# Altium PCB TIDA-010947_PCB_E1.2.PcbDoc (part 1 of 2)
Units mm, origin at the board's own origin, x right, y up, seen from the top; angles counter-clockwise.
Board outline 34 x 34 mm, 4 copper layers (Top Layer, GND, PWR, Bottom Layer), stack 1.787 mm thick; 64 components, 51 nets, 201 pads, 60 vias.
Unrouted connection lines stored in the file: 1.
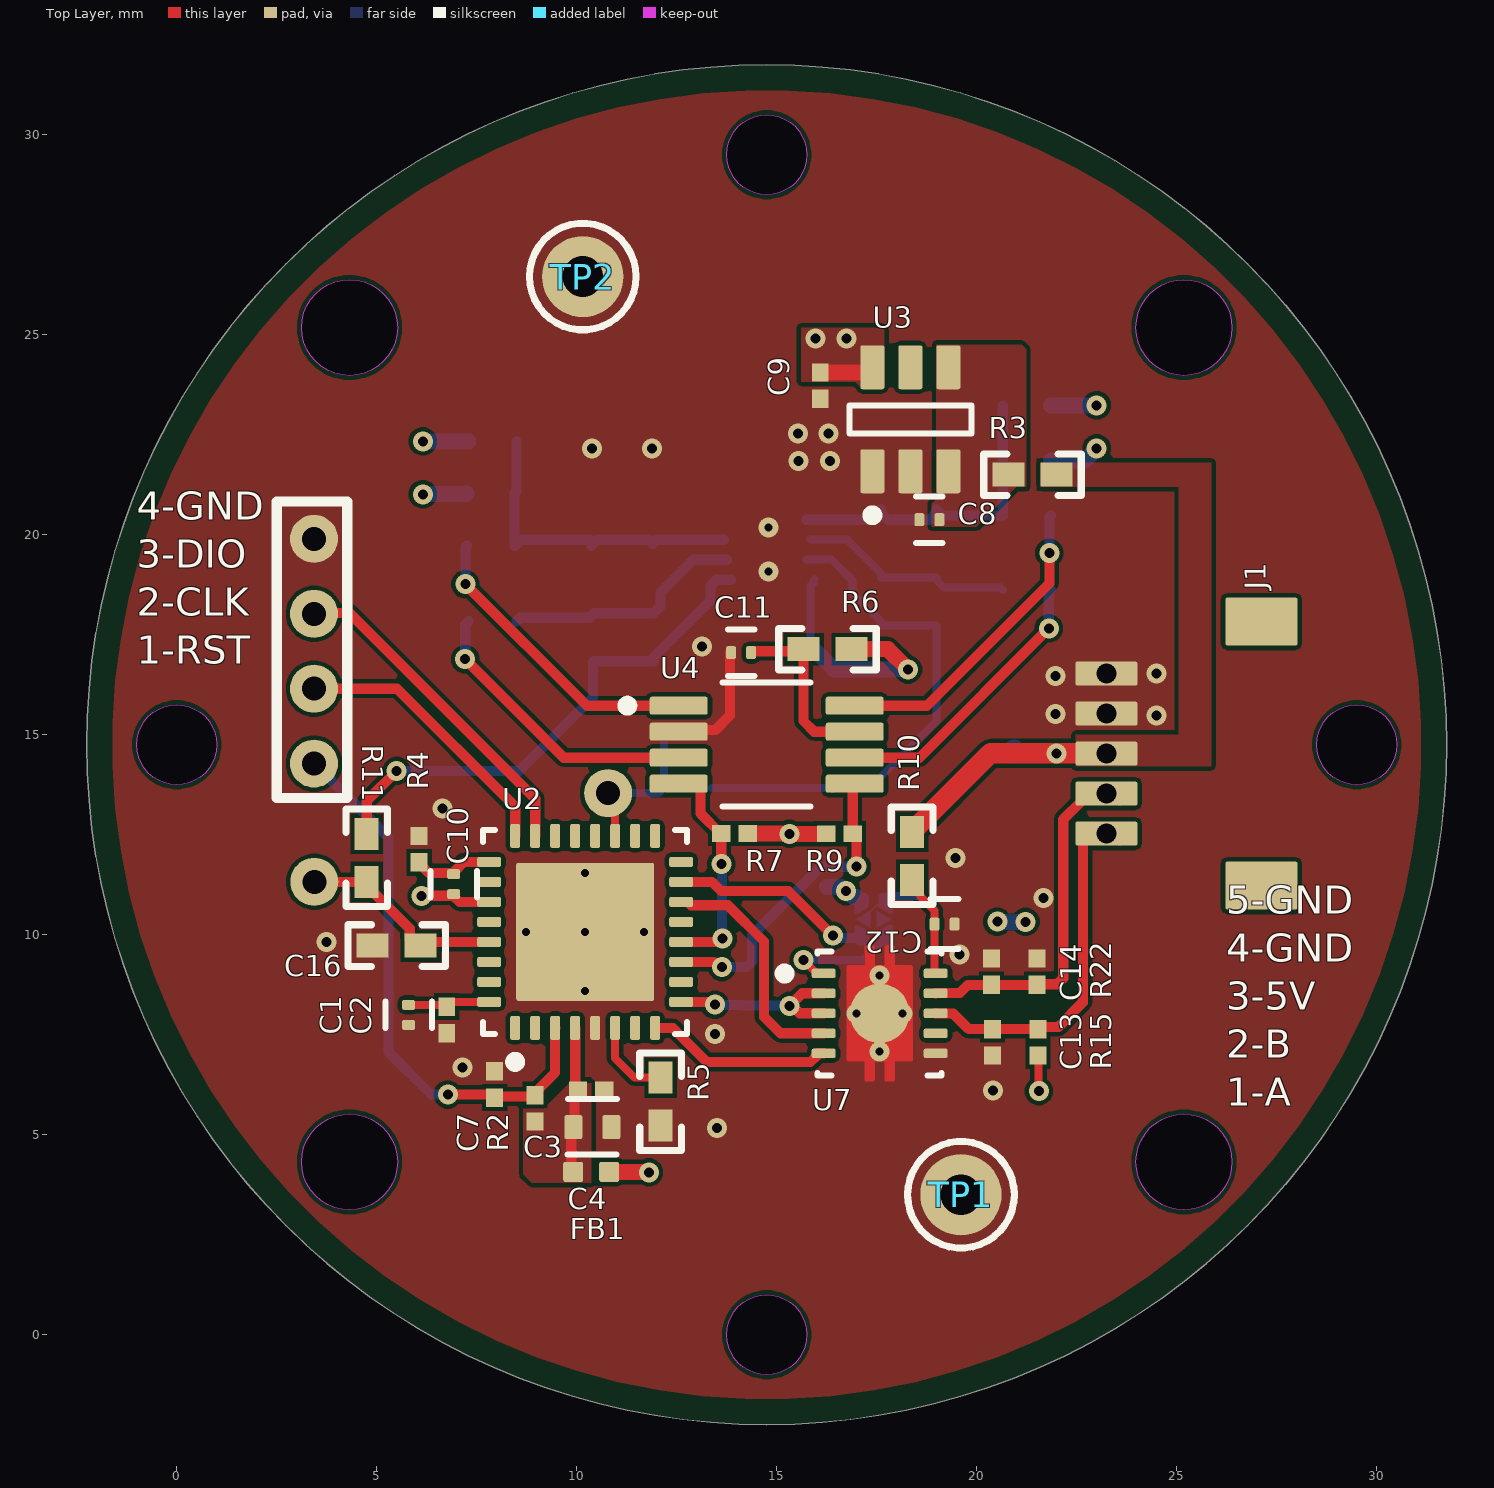
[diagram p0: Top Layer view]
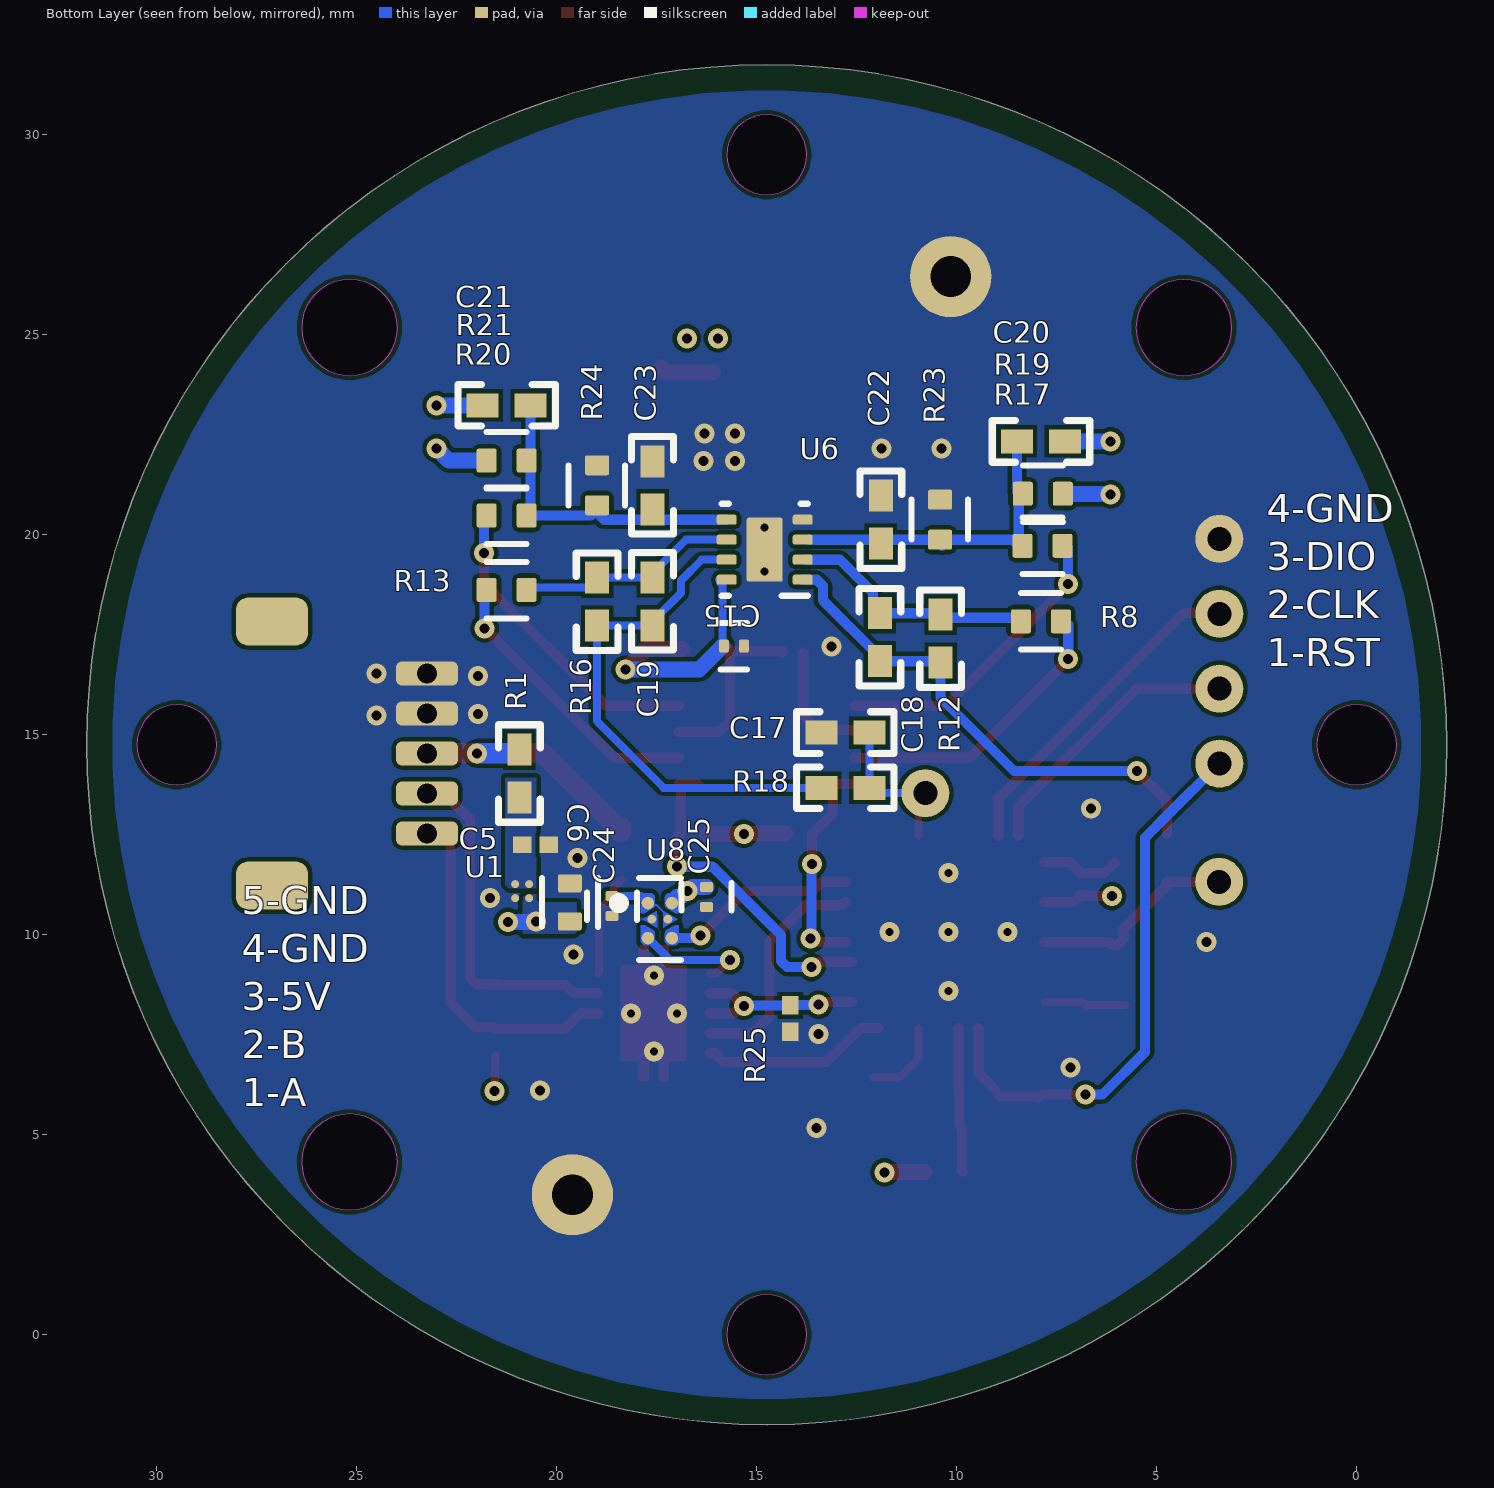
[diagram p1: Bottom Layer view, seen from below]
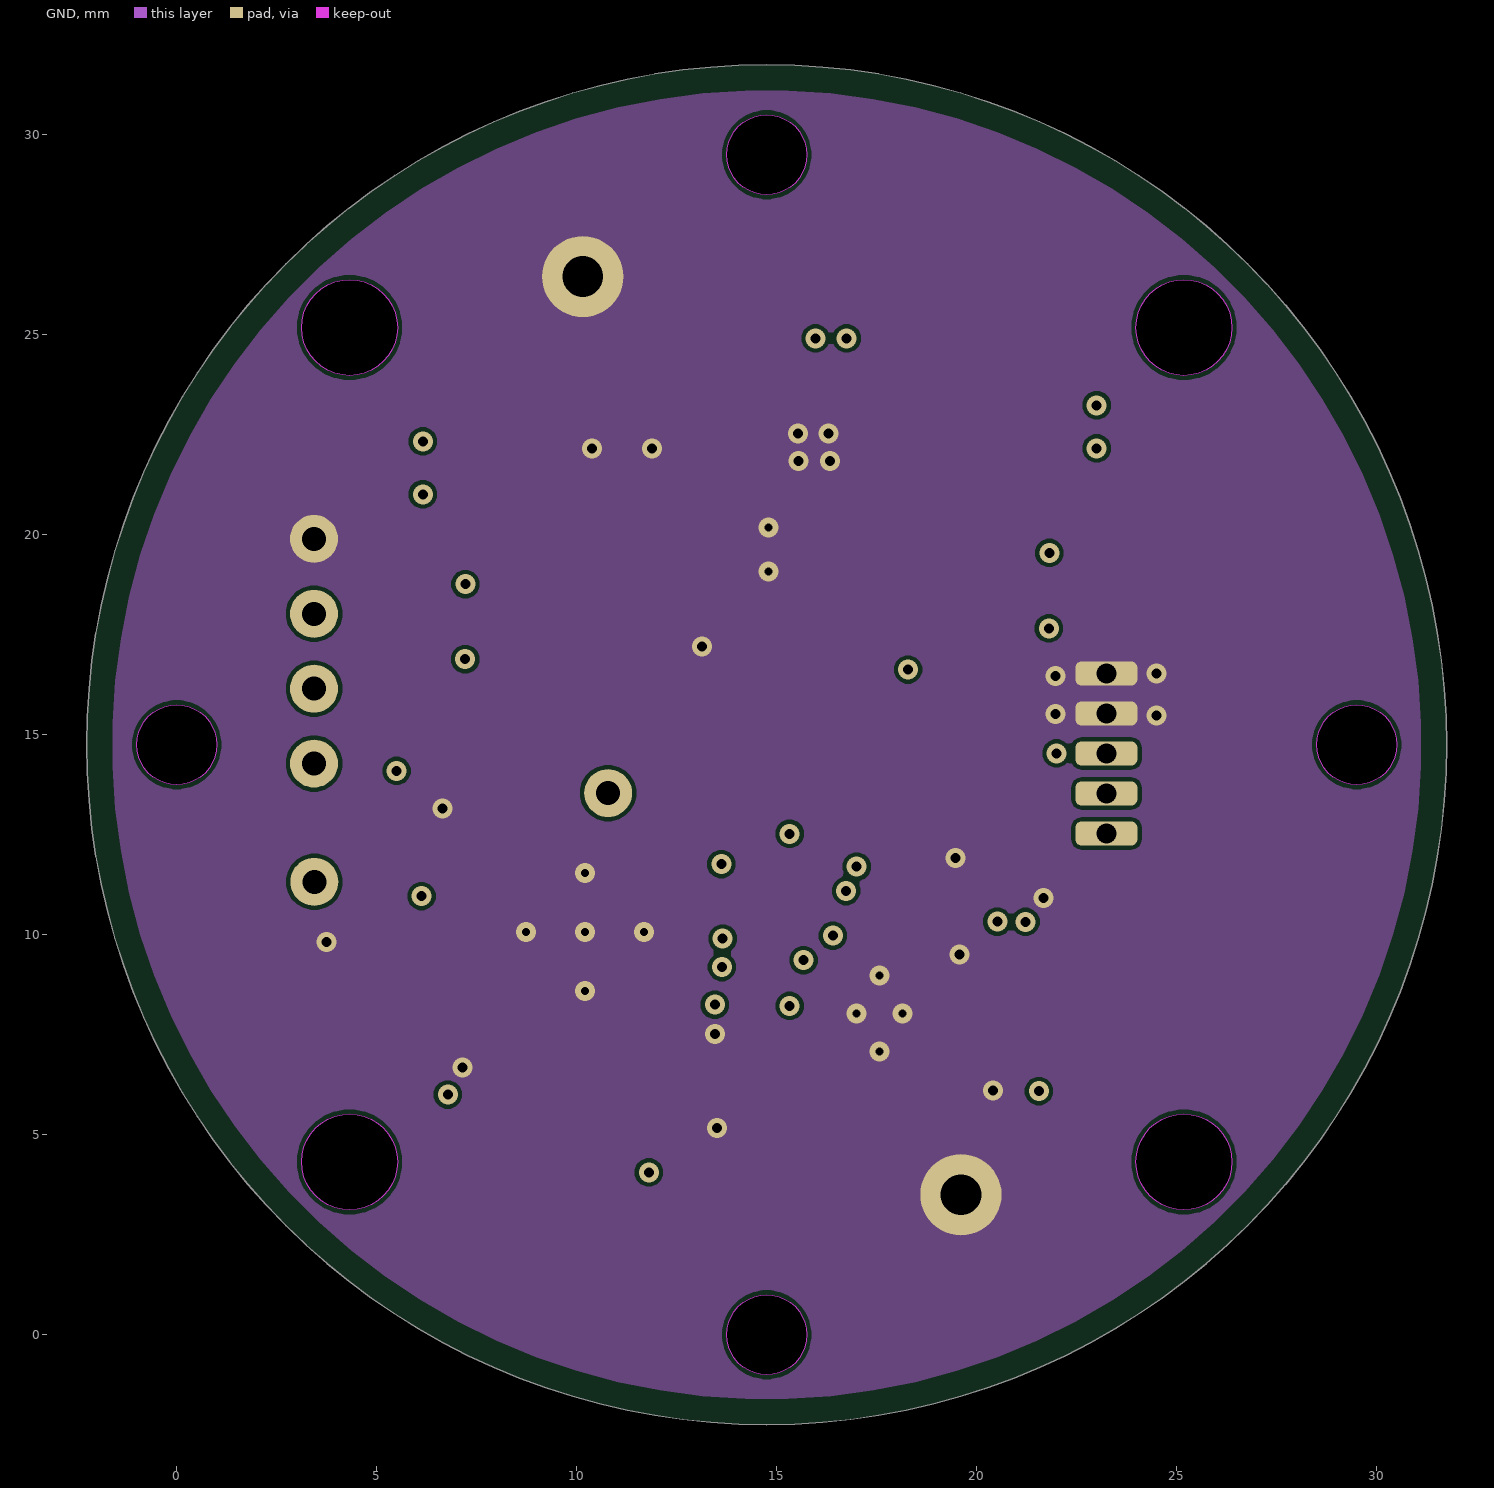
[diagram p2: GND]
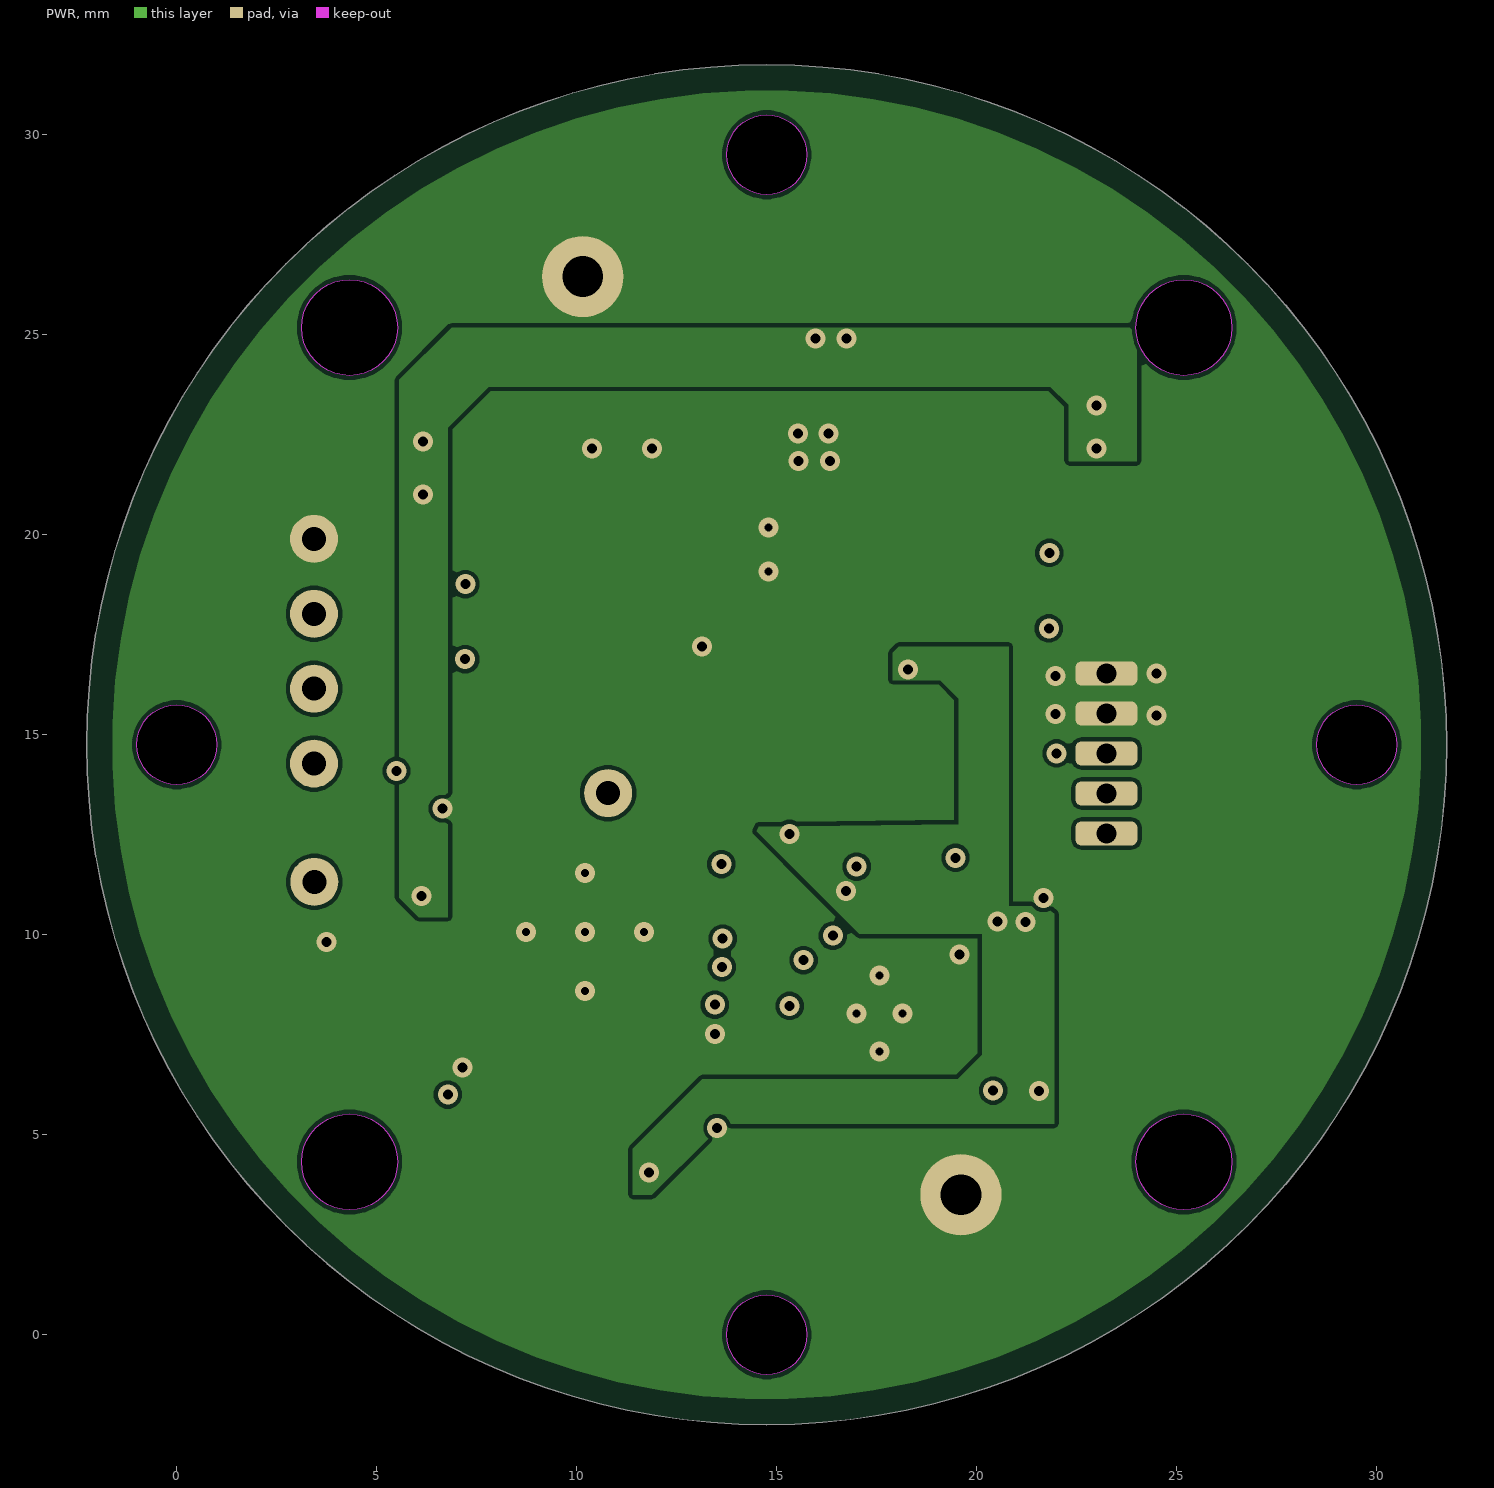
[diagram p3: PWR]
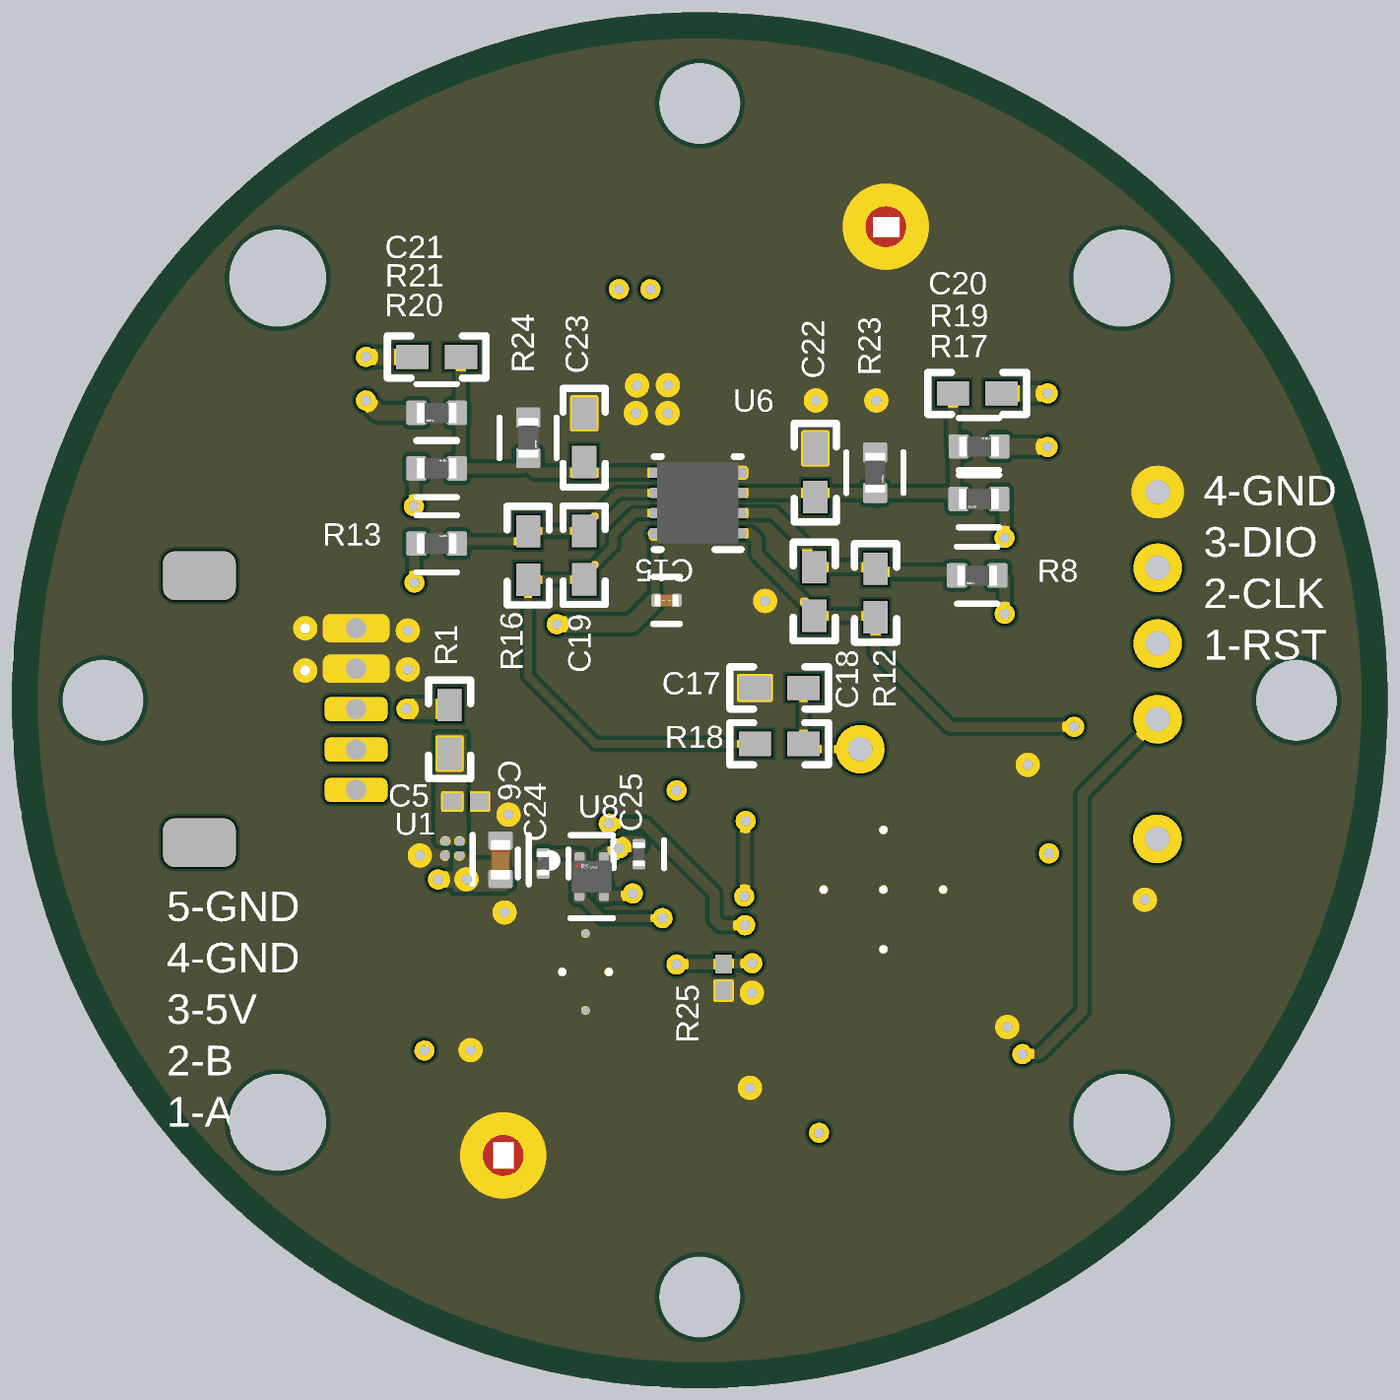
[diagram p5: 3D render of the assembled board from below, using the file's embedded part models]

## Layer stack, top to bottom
Top Solder: solder mask 0.0102, Solder Resist, Dk 3.5
Top Layer: signal copper 0.0356
Dielectric 1: prepreg 0.0711, PP-006, Dk 4.1
GND: signal copper 0.035
Dielectric1: core 1.5037, FR-4 High Tg, Dk 4.8
PWR: signal copper 0.035
Dielectric 2: prepreg 0.0711, PP-006, Dk 4.1
Bottom Layer: signal copper 0.0356
Bottom Solder: solder mask 0.0102, Solder Resist, Dk 3.5

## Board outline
14.75,-2.25 cw(c14.75,14.75) -2.25,14.75 cw(c14.75,14.75) 14.75,31.75 cw(c14.75,14.75) 31.75,14.75 cw(c14.75,14.75)
cut-out: 0,13.75 cw(c0,14.75) -1,14.75 cw(c0,14.75) 0,15.75 cw(c0,14.75) 1,14.75 cw(c0,14.75)
cut-out: 29.5,13.75 cw(c29.5,14.75) 28.5,14.75 cw(c29.5,14.75) 29.5,15.75 cw(c29.5,14.75) 30.5,14.75 cw(c29.5,14.75)
cut-out: 4.32,3.12 cw(c4.32,4.32) 3.12,4.32 cw(c4.32,4.32) 4.32,5.52 cw(c4.32,4.32) 5.52,4.32 cw(c4.32,4.32)
cut-out: 25.18,23.98 cw(c25.18,25.18) 23.98,25.18 cw(c25.18,25.18) 25.18,26.38 cw(c25.18,25.18) 26.38,25.18 cw(c25.18,25.18)
cut-out: 14.75,28.5 cw(c14.75,29.5) 13.75,29.5 cw(c14.75,29.5) 14.75,30.5 cw(c14.75,29.5) 15.75,29.5 cw(c14.75,29.5)
cut-out: 4.32,23.98 cw(c4.32,25.18) 3.12,25.18 cw(c4.32,25.18) 4.32,26.38 cw(c4.32,25.18) 5.52,25.18 cw(c4.32,25.18)
cut-out: 14.75,-1 cw(c14.75,0) 13.75,0 cw(c14.75,0) 14.75,1 cw(c14.75,0) 15.75,0 cw(c14.75,0)
cut-out: 25.18,3.12 cw(c25.18,4.32) 23.98,4.32 cw(c25.18,4.32) 25.18,5.52 cw(c25.18,4.32) 26.38,4.32 cw(c25.18,4.32)

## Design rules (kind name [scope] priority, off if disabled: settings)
AcuteAngle [All] p1: minimum=4.50000000000000E+0001 checktracksonly=FALSE
AssemblyTestPointUsage [All] p1: valid=2
BoardOutlineClearance BoardOutlineClearance_MountingHoles [OnCopper and InComponentClass('Mounting Holes')] p1: gap=1 ignorepadtopadclearanceinfootprint=FALSE
BoardOutlineClearance BoardOutlineClearance_Poly [OnCopper and IsPoly] p2: gap=0.635 ignorepadtopadclearanceinfootprint=FALSE
BoardOutlineClearance [OnCopper and Not InComponentClass('Logo') and not InComponentClass('FiducialMark') and not InRegion(1000,500,4000,800) and not InPoly] p3: gap=1.016 ignorepadtopadclearanceinfootprint=FALSE
Clearance Clearance_Keepouts [((IsTrack Or IsArc) And Not InPoly) And IsFree and IsKeepOut vs ((IsTrack Or IsArc) And Not InPoly) And IsFree and IsKeepOut] p1: gap=0 ignorepadtopadclearanceinfootprint=FALSE
Clearance Clearance_Poly [InPolygon] p2: gap=0.1 ignorepadtopadclearanceinfootprint=TRUE
Clearance Clearance_FiducialMark [IsKeepOut and InComponentClass('FiducialMark') vs IsPad and InComponentClass('FiducialMark')] p3: gap=0 ignorepadtopadclearanceinfootprint=FALSE
Clearance [All] p4: gap=0.05 ignorepadtopadclearanceinfootprint=TRUE
ComponentClearance ComponentClearance_MountingHoles_FiducialMarks [InComponentClass('Mounting Holes') vs InComponentClass('FiducialMark')] p1: gap=1.27 collisioncheckmode=3 verticalgap=0.254 showdistances=FALSE
ComponentClearance ComponentClearance_Shunt [InComponentClass('Header') vs InComponentClass('Shunt')] p2: gap=0 collisioncheckmode=3 verticalgap=0 showdistances=FALSE
ComponentClearance ComponentClearance_Logo [InComponentClass('Logo')] p3: gap=0.762 collisioncheckmode=3 verticalgap=0.254 showdistances=FALSE
ComponentClearance ComponentClearance_ScrewToNut [(HasFootprint('NY PMS 440 0025 PH')) vs (HasFootprint('Keystone_1902C'))] p4: gap=0.127 collisioncheckmode=3 verticalgap=0.254 showdistances=FALSE
ComponentClearance ComponentClearance_MountingHoles [InComponentClass('Mounting Holes')] p5: gap=2.54 collisioncheckmode=3 verticalgap=2540 showdistances=FALSE
ComponentClearance ComponentClearance_SmallPassives [HasFootprint('0201*') or HasFootprint('0402*') or HasFootprint('0508') or HasFootprint('0603*') or HasFootprint('0612') or HasFootprint('0805*') or HasFootprint('0815*') or HasFootprint('0830*') or HasFootprint('1206*') or HasFootprint('1210*') or HasFootprint('1808*') or HasFootprint('1812*') or HasFootprint('1825*') or HasFootprint('2010*') or HasFootprint('2220*') or HasFootprint('2225*') or HasFootprint('2512*') or HasFootprint('2728*') or HasFootprint('3518*') vs HasFootprint('0201*') or HasFootprint('0402*') or HasFootprint('0508') or HasFootprint('0603*') or HasFootprint('0612') or HasFootprint('0805*') or HasFootprint('0815*') or HasFootprint('0830*') or HasFootprint('1206*') or HasFootprint('1210*') or HasFootprint('1808*') or HasFootprint('1812*') or HasFootprint('1825*') or HasFootprint('2010*') or HasFootprint('2220*') or HasFootprint('2225*') or HasFootprint('2512*') or HasFootprint('2728*') or HasFootprint('3518*')] p6: gap=0.38 collisioncheckmode=3 verticalgap=0.254 showdistances=FALSE
ComponentClearance ComponentClearance_THtoSMT [IsThruComponent vs IsSMTComponent] p7: gap=0.762 collisioncheckmode=3 verticalgap=0.762 showdistances=FALSE
ComponentClearance ComponentClearance_THtoTH [IsThruComponent vs IsThruComponent] p8: gap=0.508 collisioncheckmode=3 verticalgap=0.762 showdistances=FALSE
ComponentClearance [All] p9: gap=0.508 collisioncheckmode=3 verticalgap=0.254 showdistances=FALSE
DiffPairsRouting [All] p1: maxlimit=2.54 minlimit=0.254 mostfreqgap=0.254 toplayer_minwidth=0.381 toplayer_maxwidth=0.381 toplayer_prefwidth=0.381 midlayer1_minwidth=0.381 midlayer1_maxwidth=0.381 midlayer1_prefwidth=0.381 midlayer2_minwidth=0.381 midlayer2_maxwidth=0.381 midlayer2_prefwidth=0.381 bottomlayer_minwidth=0.381 bottomlayer_maxwidth=0.381 bottomlayer_prefwidth=0.381 maxuncoupledlength=25.4
FabricationTestPointUsage TestPointUsage [All] p1: valid=2 allowmultiple=FALSE
FabricationTestpoint Testpoint [All] p1: side=3 testpointundercomponent=TRUE minsize=1.016 maxsize=2.54 preferedsize=1.524 minholesize=0 maxholesize=1.016 preferedholesize=0.813 testpointgrid=0.025 allowsidetop=TRUE allowsidebottom=TRUE usegrid=TRUE gridtolerance=0
FanoutControl Fanout_LCC [IsLCC] p1: bgadir=Out bgaviamode=Centered fanoutstyle=Auto fanoutdirection=Alternating viagrid=0.025 // Fanout_LCC (Default Rule)
FanoutControl Fanout_BGA [IsBGA] p2: bgadir=Out bgaviamode=Centered fanoutstyle=Auto fanoutdirection=Alternating viagrid=0.025 // Fanout_BGA (Default Rule)
FanoutControl Fanout_Default [All] p4: bgadir=Out bgaviamode=Centered fanoutstyle=Auto fanoutdirection=Alternating viagrid=0.025 // Fanout_Default (Default Rule)
FanoutControl Fanout_Small [(CompPinCount < 5)] p5: bgadir=Out bgaviamode=Centered fanoutstyle=Auto fanoutdirection=OutThenIn viagrid=0.025 // Fanout_Small (Default Rule)
HoleSize [All] p1: absolutevalues=TRUE maxlimit=6.375 minlimit=0.2 maxpercent=80.000 minpercent=20.000
MinimumAnnularRing MinimumAnnularRing_ThermalPadVias [IsVia and InAnyComponent] p1: minimumring=0.15
MinimumAnnularRing [All] p2: minimumring=0.1
MinimumSolderMaskSliver MinimumSolderMaskSliver_Logo [InComponentClass('Logo') vs InComponentClass('Logo')] p1: minsoldermaskwidth=0.018
MinimumSolderMaskSliver [All] p2: minsoldermaskwidth=0.08
PlaneConnect [All] p1: planeconnectstyle=Relief reliefexpansion=0.254 reliefentries=4 reliefconductorwidth=0.254 reliefairgap=0.254
PolygonConnect [All] p1: connectstyle=Direct reliefconductorwidth=0.254 reliefentries=4 polygonreliefangle="90 Angle" airgapwidth=0.254
RoutingLayers [All] p1: top layer_v5=TRUE mid layer 1_v5=FALSE mid layer 2_v5=FALSE bottom layer_v5=TRUE
RoutingVias ThermalPadVias [IsVia and InAnyComponent] p1: holewidth=0.2 width=0.5 viastyle="Through Hole" minholewidth=0.2 minwidth=0.5 maxholewidth=0.33 maxwidth=0.6
RoutingVias [All] p2: holewidth=0.406 width=0.864 viastyle="Through Hole" minholewidth=0.2 minwidth=0.4 maxholewidth=1.016 maxwidth=1.651
SilkToBoardRegionClearance [Not ((IsComment or IsDesignator) And (Hide <> 'False')) and not InRegion(1000,500,4000,800)] p1:
SilkToSilkClearance SilkToSilkClearance_Pb-FreeLogo [(HasFootprint('Pb-Free_Overlay_Medium') OR HasFootprint('Pb-Free_Overlay_Small')) vs (HasFootprint('Pb-Free_Overlay_Medium') OR HasFootprint('Pb-Free_Overlay_Small'))] p1: silktosilkclearance=0
SilkToSilkClearance [All] p2: silktosilkclearance=0.1
SilkToSolderMaskClearance SilkToComponentPadClearance [(IsPad or IsFill or IsRegion) and InAnycomponent] p1: minsilkscreentomaskgap=0.127 clearancetoexposedcopper=TRUE
SilkToSolderMaskClearance "Silk to Solder Mask Opening" [All] p2: minsilkscreentomaskgap=0.1 clearancetoexposedcopper=FALSE
SolderMaskExpansion [All] p1: expansion=0.05 istentingtop=FALSE
UnRoutedNet [All] p1: checkbadconnections=TRUE
Width [All] p1: maxlimit=2.54 minlimit=0.05 preferedwidth=0.254 checkconnectedcopper=TRUE
13 further rules are at their usual default settings.

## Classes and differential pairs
component class TIDA-010947_Hardware: ZZ1 ZZ2 ZZ3 ZZ4
component class AssemblyNote: ZZ1 ZZ2 ZZ3 ZZ4

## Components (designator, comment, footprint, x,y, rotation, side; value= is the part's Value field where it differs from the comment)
C1 "LMK063BJ104KP-F" FP-LMK063BJ104KP-F_0201-MFG 5.797,7.996 r270 top value=100nF
C2 "CL03A474KQ3NNNC" 0201_033 6.749,7.871 r90 top value=0.47uF
C3 "ZRB15XC80J106ME05D" FP-ZRB15XC80J106ME05D_0402-MFG 10.391,5.189 r0 top value=10µF
C4 "CL03A105MP3NSNC" 0201 10.362,6.124 r180 top value=1uF
C5 "CL03A105MP3NSNC" 0201 20.534,12.247 r180 bottom value=1uF
C6 "ZRB15XC80J106ME05D" FP-ZRB15XC80J106ME05D_0402-MFG 19.673,10.808 r270 bottom value=10µF
C7 "GRM033R60J103KA01D" 0201 7.948,6.259 r90 top value=0.01uF
C8 "LMK063BJ104KP-F" FP-LMK063BJ104KP-F_0201-MFG 18.817,20.375 r0 top value=100nF
C9 "CL03A105MP3NSNC" 0201 16.09,23.726 r270 top value=1uF
C10 "LMK063BJ104KP-F" FP-LMK063BJ104KP-F_0201-MFG 6.923,11.265 r90 top value=100nF
C11 "LMK063BJ104KP-F" FP-LMK063BJ104KP-F_0201-MFG 14.11,17.052 r0 top value=100nF
C12 "JMK063BC6105MP-F" FP-JMK063BC6105MP-F_0201-MFG 19.195,10.265 r180 top
C13 "CGA1A2X7R1H331K030BA" 0201_033 20.395,7.31 r90 top value=330pF
C14 "CGA1A2X7R1H331K030BA" 0201_033 20.369,9.075 r90 top value=330pF
C15 "LMK063BJ104KP-F" FP-LMK063BJ104KP-F_0201-MFG 15.57,17.218 r0 bottom value=100nF
C16 "CGA2B2X8R1H102K050BA" 0402 5.497,9.727 r180 top value=1000pF
C17 "CGA2B2X8R1H102K050BA" 0402 12.787,15.054 r0 bottom value=1000pF
C18 "C0402C100K4GACTU" 0402 11.919,17.437 r90 bottom value=10pF
C19 "C0402C100K4GACTU" 0402 17.605,18.335 r90 bottom value=10pF
C20 "GRM1555C1H5R0CA01D" 0402 7.894,22.333 r0 bottom value=5pF
C21 "GRM1555C1H5R0CA01D" 0402 21.252,23.235 r180 bottom value=5pF
C22 "GRM1555C1H5R0CA01D" 0402 11.894,20.375 r90 bottom value=5pF
C23 "GRM1555C1H5R0CA01D" 0402 17.605,21.237 r90 bottom value=5pF
C24 "JMK063BC6105MP-F" FP-JMK063BC6105MP-F_0201-MFG 18.62,10.717 r90 bottom
C25 "JMK063BC6105MP-F" FP-JMK063BC6105MP-F_0201-MFG 16.255,10.945 r90 bottom
FB1 "MPZ1005S121HT000" FP-MPZ1005S121HT000_0402-MFG 10.362,4.07 r0 top
J1 "SM05B-SRSS-TB(LF)(SN)" JST_SM05B-SRSS-TB 25.18,14.53 r90 top
R1 "RC0402JR-070RL" 0402 20.934,14.03 r270 bottom value=0
R2 "RK73H1HTTC4702F" 0201 8.96,5.659 r270 top value=47.0k
R3 "RC0402JR-070RL" 0402 21.395,21.5 r180 top value=0
R4 "ERJ-1GN0R00C" 0201 6.061,12.138 r270 top value=0
R5 "RG1005P-104-B-T5" 0402 12.096,5.824 r90 top value=100k
R6 "RC0402JR-070RL" 0402 16.27,17.137 r180 top value=0
R7 "RC0201DR-07100KL" 0201 13.945,12.53 r0 top value=100k
R8 "RT0402BRB0710KL" FP-RT0402BRB0710KL_0402-MFG 7.894,17.835 r0 bottom value=10k
R9 "RC0201DR-07100KL" 0201 16.57,12.523 r180 top value=100k
R10 "RC0402JR-070RL" 0402 18.384,11.973 r270 top value=0
R11 "RMCF0402JT100R" 0402 4.75,11.923 r270 top value=100
R12 "PNM0402E5001BST1" 0402 10.404,17.402 r270 bottom value=5.00k
R13 "RT0402BRB0710KL" FP-RT0402BRB0710KL_0402-MFG 21.252,18.622 r180 bottom value=10k
R15 "RC0201DR-07100KL" 0201 21.53,7.31 r270 top value=100k
R16 "PNM0402E5001BST1" 0402 18.99,18.325 r270 bottom value=5.00k
R17 "RT0402BRB0710KL" FP-RT0402BRB0710KL_0402-MFG 7.852,19.724 r0 bottom value=10k
R18 "RMCF0402JT100R" 0402 12.787,13.674 r180 bottom value=100
R19 "RT0402BRB0710KL" FP-RT0402BRB0710KL_0402-MFG 7.848,21.024 r180 bottom value=10k
R20 "RT0402BRB0710KL" FP-RT0402BRB0710KL_0402-MFG 21.252,20.479 r180 bottom value=10k
R21 "RT0402BRB0710KL" FP-RT0402BRB0710KL_0402-MFG 21.252,21.853 r0 bottom value=10k
R22 "RC0201DR-07100KL" 0201 21.504,9.075 r270 top value=100k
R23 "RT0402BRB0710KL" FP-RT0402BRB0710KL_0402-MFG 10.417,20.375 r270 bottom value=10k
R24 "RT0402BRB0710KL" FP-RT0402BRB0710KL_0402-MFG 18.99,21.237 r270 bottom value=10k
R25 "RC0201DR-0710KL" 0201 14.161,7.904 r90 bottom value=10.0k
TP1 "5000" Keystone5000 19.606,3.5 r0 top
TP2 "5000" Keystone5000 10.151,26.454 r90 top
U1 "TPS7A0533PYKAR" YKA0004AAAA 20.864,11.088 r270 bottom
U2 "MSPM0G3507SRHB" RHB0032E-MFG 10.212,10.07 r90 top
U3 "REF35330QDBVR" DBV0006A-MFG 18.34,22.887 r90 top
U4 "TMAG6180EDGKRQ1" DGK0008A-MFG 14.75,14.75 r0 top
U6 "TLV9062IDSGR" DSG0008A 14.8,19.625 r0 bottom
U7 "THVD1454DRC" DRC0010J-MFG 17.574,8.035 r0 top
U8 "TXU0101DTQR" DTQ0006A-MFG 17.42,10.39 r180 bottom
ZZ1 "This Assembly Note is for PCB labels only" AssemblyNoteLabel 4.699,100.025 r0 top
ZZ2 "These assemblies are ESD sensitive, ESD precautions shall be observed." AssemblyNote 4.699,97.259 r0 top
ZZ3 "These assemblies must be clean and free from flux and all contaminants. Use of no clean flux is not acceptable." AssemblyNote 4.699,95.01 r0 top
ZZ4 "These assemblies must comply with workmanship standards IPC-A-610 Class 2, unless otherwise specified." AssemblyNote 4.699,92.761 r0 top

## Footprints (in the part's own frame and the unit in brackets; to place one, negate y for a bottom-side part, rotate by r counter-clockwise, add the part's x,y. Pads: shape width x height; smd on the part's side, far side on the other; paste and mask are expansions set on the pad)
0201 [mm] "Data from Kemet datasheet CC101_COM dated 7/28/11"
  rect 0.46x0.42 smd mask+0.048: 1(-0.33,0) 2(0.33,0)
  body extent -0.31,-0.16 0.31,0.16, height 0.26
0201_033 [mm] "SMD, 2-Leads, Height 0.33mm"
  rect 0.46x0.42 smd mask+0.048: 1(-0.33,0) 2(0.33,0)
  body extent -0.31,-0.16 0.31,0.16, height 0.33
0402 [mm] "0402 from SM-752 data"
  rect 0.8x0.6 smd: 1(-0.6,0) 2(0.6,0)
  silkscreen extent -1.22,-0.52 1.22,0.52, body extent -0.55,-0.3 0.55,0.3, height 0.6
AssemblyNote [mm] "Assembly Note"
AssemblyNoteLabel [mm] "Assembly Note for PCB Labels"
DBV0006A-MFG [mm]
  rrect17% 1.1x0.6 smd paste+0 mask+0: 1(-1.3,0.95) 2(-1.3,0) 3(-1.3,-0.95) 4(1.3,-0.95) 5(1.3,0) 6(1.3,0.95)
  silkscreen extent -2.52,-1.53 0.35,1.53, body extent -1.95,-1.78 1.95,1.78, height 0.25
DGK0008A-MFG [mm]
  rrect22% 1.45x0.45 smd paste+0 mask+0: 1(-2.2,0.975) 2(-2.2,0.325) 3(-2.2,-0.325) 4(-2.2,-0.975) 5(2.2,-0.975) 6(2.2,-0.325) 7(2.2,0.325) 8(2.2,0.975)
  silkscreen extent -3.61,-1.55 1.1,1.55, body extent -2.45,-1.5 2.45,1.5, height 1.1
DRC0010J-MFG [mm]
  rrect42% 0.6x0.24 smd paste+0 mask+0: 1(-1.4,1) 2(-1.4,0.5) 3(-1.4,0) 4(-1.4,-0.5) 5(-1.4,-1) 6(1.4,-1) 7(1.4,-0.5) 8(1.4,0) 9(1.4,0.5) 10(1.4,1)
  round 1.485 smd paste-1000 mask+0: 11(0,0)
  Top Layer region: -0.825,-1.15 -0.818,-1.175 -0.8,-1.193 -0.775,-1.2 -0.775,-1.2 -0.375,-1.2 -0.375,-1.65 -0.368,-1.675 -0.35,-1.693 -0.325,-1.7 -0.325,-1.7 -0.175,-1.7 -0.156,-1.696 -0.14,-1.685 -0.129,-1.669 -0.125,-1.65 -0.125,-1.65 -0.125,-1.2 0.125,-1.2 0.125,-1.65 0.129,-1.669 0.14,-1.685 0.156,-1.696 0.175,-1.7 0.175,-1.7 0.325,-1.7 0.35,-1.693 0.368,-1.675 0.375,-1.65 0.375,-1.65 0.375,-1.2 0.775,-1.2 0.8,-1.193 0.818,-1.175 0.825,-1.15 0.825,-1.15 0.825,1.15 0.818,1.175 0.8,1.193 0.775,1.2 0.775,1.2 0.375,1.2 0.375,1.65 0.368,1.675 0.35,1.693 0.325,1.7 0.325,1.7 0.175,1.7 0.156,1.696 0.14,1.685 0.129,1.669 0.125,1.65 0.125,1.65 0.125,1.2 -0.125,1.2 -0.125,1.65 -0.129,1.669 -0.14,1.685 -0.156,1.696 -0.175,1.7 -0.175,1.7 -0.325,1.7 -0.35,1.693 -0.368,1.675 -0.375,1.65 -0.375,1.65 -0.375,1.2 -0.775,1.2 -0.8,1.193 -0.818,1.175 -0.825,1.15 -0.825,1.15
  silkscreen extent -2.5,-1.55 1.55,1.55, body extent -1.8,-1.8 1.8,1.8, height 0.25
DSG0008A [mm] "SON, 8-Leads, Body 2x2mm, Pitch 0.5mm, Thermal Pad 1.6x0.9mm, TI Recommended"
  rrect40% 0.5x0.25 smd: 1(-0.95,0.75) 2(-0.95,0.25) 3(-0.95,-0.25) 4(-0.95,-0.75) 5(0.95,-0.75) 6(0.95,-0.25) 7(0.95,0.25) 8(0.95,0.75)
  rrect14% 0.9x0.7 on Bottom Paste: 9(0,-0.45) 9(0,0.45)
  rrect11% 0.9x1.6 smd paste-0.45: 9(0,0)
  silkscreen extent -1.07,-1.15 1.07,1.15, body extent -1,-1 1,1, height 0.77
DTQ0006A-MFG [mm]
  round 0.314 smd paste-1000 mask-1000: 1(-0.3,0.4) 6(0.3,0.4)
  round 0.22 smd paste-1000 mask-1000: 2(-0.2,0) 5(0.2,0)
  round 0.315 smd paste-1000 mask-1000: 3(-0.3,-0.475) 4(0.3,-0.475)
  Top Layer region: 0.475,0.15 0.475,0.55 0.467,0.588 0.446,0.621 0.413,0.642 0.375,0.65 0.375,0.65 0.225,0.65 0.187,0.642 0.154,0.621 0.133,0.588 0.125,0.55 0.125,0.55 0.125,0.358 0.131,0.323 0.148,0.293 0.175,0.271 0.175,0.271 0.385,0.15
  Top Layer region: 0.475,-0.15 0.475,-0.55 0.467,-0.588 0.446,-0.621 0.413,-0.642 0.375,-0.65 0.375,-0.65 0.225,-0.65 0.187,-0.642 0.154,-0.621 0.133,-0.588 0.125,-0.55 0.125,-0.55 0.125,-0.358 0.131,-0.323 0.148,-0.293 0.175,-0.271 0.175,-0.271 0.385,-0.15
  Top Layer region: -0.475,-0.15 -0.475,-0.55 -0.467,-0.588 -0.446,-0.621 -0.413,-0.642 -0.375,-0.65 -0.375,-0.65 -0.225,-0.65 -0.175,-0.637 -0.138,-0.6 -0.125,-0.55 -0.125,-0.55 -0.125,-0.358 -0.131,-0.323 -0.148,-0.293 -0.175,-0.271 -0.175,-0.271 -0.385,-0.15
  Top Layer region: -0.475,0.15 -0.475,0.55 -0.462,0.6 -0.425,0.637 -0.375,0.65 -0.375,0.65 -0.225,0.65 -0.175,0.637 -0.138,0.6 -0.125,0.55 -0.125,0.55 -0.125,0.358 -0.131,0.323 -0.148,0.293 -0.175,0.271 -0.175,0.271 -0.385,0.15
  Top Layer region: 0.078,-0.212 0.444,0 0.078,0.212
  Top Layer region: -0.078,-0.212 -0.444,0 -0.078,0.212
  silkscreen extent -1.15,-1.02 0.53,1.02, body extent -0.5,-0.4 0.5,0.4, height 0.4
FP-JMK063BC6105MP-F_0201-MFG [mm]
  rrect40% 0.25x0.325 smd paste+0 mask+0: 1(-0.25,0) 2(0.25,0)
  silkscreen extent -0.35,-0.63 0.35,0.63, body extent -0.48,-0.3 0.48,0.3, height 0.25
FP-LMK063BJ104KP-F_0201-MFG [mm]
  rrect40% 0.25x0.325 smd paste+0 mask+0: 1(-0.25,0) 2(0.25,0)
  silkscreen extent -0.33,-0.58 0.33,0.58, body extent -0.48,-0.27 0.48,0.27, height 0.25
FP-MPZ1005S121HT000_0402-MFG [mm]
  rrect20% 0.5x0.5 smd paste+0 mask+0: 1(-0.45,0) 2(0.45,0)
  body extent -0.8,-0.38 0.8,0.38, height 0.25
FP-RT0402BRB0710KL_0402-MFG [mm]
  rrect20% 0.5x0.6 smd paste+0 mask+0: 1(-0.5,0) 2(0.5,0)
  silkscreen extent -0.5,-0.71 0.5,0.7, body extent -0.5,-0.25 0.5,0.25, height 0.35
FP-ZRB15XC80J106ME05D_0402-MFG [mm]
  rrect22% 0.45x0.6 smd paste+0 mask+0: 1(-0.475,0) 2(0.475,0)
  silkscreen extent -0.62,-0.69 0.61,0.7, body extent -0.8,-0.45 0.8,0.45, height 0.25
JST_SM05B-SRSS-TB [mm] "Header (Shrouded), 1 mm, 5x1, R/A, SMT"
  rrect17% 0.6x1.55 smd: 1(-2,1.938) 2(-1,1.938) 3(0,1.938) 4(1,1.938) 5(2,1.938)
  rrect8% 1.2x1.8 smd: MP1(-3.3,-1.937) MP2(3.3,-1.937)
  body extent -3.5,-2.64 3.5,2.31, height 2.97
Keystone5000 [mil] "For Keystone 500x miniature loop terminals"
  round 80 hole 40: 1(0,0)
  silkscreen extent -52,-52 52,52, body extent -49,-49 49,49, height 182
RHB0032E-MFG [mm]
  rrect40% 0.6x0.25 smd paste+0 mask+0: 1(-2.4,1.75) 2(-2.4,1.25) 3(-2.4,0.75) 4(-2.4,0.25) 5(-2.4,-0.25) 6(-2.4,-0.75) 7(-2.4,-1.25) 8(-2.4,-1.75) 17(2.4,-1.75) 18(2.4,-1.25) 19(2.4,-0.75) 20(2.4,-0.25) 21(2.4,0.25) 22(2.4,0.75) 23(2.4,1.25) 24(2.4,1.75)
  rrect40% 0.25x0.6 smd paste+0 mask+0: 9(-1.75,-2.4) 10(-1.25,-2.4) 11(-0.75,-2.4) 12(-0.25,-2.4) 13(0.25,-2.4) 14(0.75,-2.4) 15(1.25,-2.4) 16(1.75,-2.4) 25(1.75,2.4) 26(1.25,2.4) 27(0.75,2.4) 28(0.25,2.4) 29(-0.25,2.4) 30(-0.75,2.4) 31(-1.25,2.4) 32(-1.75,2.4)
  rrect3% 3.45x3.45 smd paste-1000 mask+0: 33(0,0)
  silkscreen extent -3.37,-2.55 2.55,2.55, body extent -2.8,-2.8 2.8,2.8, height 0.25
YKA0004AAAA [mm] "DSBGA, 4-Balls, Body 0.7x0.7mm, Pitch 0.35mm"
  round 0.2 smd paste-0.12 mask+0.032: A1(-0.175,0.175) A2(0.175,0.175) B1(-0.175,-0.175) B2(0.175,-0.175)
  body extent -0.35,-0.35 0.35,0.35, height 0.4

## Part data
C1 C8 C10 C11 C15: library part CMP-0092661-1, "CAP CER 0.1UF 10V X5R 0201", Digikey Part Number=587-2241-1-ND, MANUFACTURER="Taiyo Yuden", Mouser Part Number=963-LMK063BJ104KP-F, Operating Temperature Range="-55°C to +85°C", TempCo=15%, Temperature Characteristic=X5R, Tolerance_%=10%, ValueDisplayed=0.1uF, Voltage=10V
C2: library part CMP-0009658-2, "CAP, CERM, 0.47 uF, 6.3 V, +/- 10%, X5R, 0201", Cap_Case=0201, MANUFACTURER="Samsung Electro-Mechanics", TempCo=X5R, Tolerance_%=10%, Value1=Unknown, Value2=6.3V, ValueDisplayed=0.47uF
C3 C6: library part CMP-0035038-1, "10µF ±20% 6.3V Ceramic Capacitor X6S 0402 (1005 Metric)", Digikey Part Number=ZRB15XC80J106ME05D-ND, MANUFACTURER=Murata, Mouser Part Number=81-ZRB15XC80J106ME5D, Operating Temperature Range="-55°C to +105°C", TempCo=22%, Temperature Characteristic=X6S, Tolerance_%=20%, ValueDisplayed=10uF
C4 C5 C9: library part CMP-0009656-3, "CAP, CERM, 1 uF, 10 V, +/- 20%, X5R, 0201", Cap_Case=0201, MANUFACTURER="Samsung Electro-Mechanics", TempCo=X5R, Tolerance_%=20%, Value1=Unknown, Value2=10V, ValueDisplayed=1uF
C7: library part CMP-0009689-1, "CAP, CERM, 0.01 uF, 6.3 V, +/- 10%, X5R, 0201", Cap_Case=0201, MANUFACTURER=MuRata, Supplier Part Number 1=490-5403-1-ND, TempCo=X5R, Tolerance_%=10%, Value1=Unknown, Value2=6.3V, ValueDisplayed=0.01uF
C12 C24 C25: library part CMP-0089441-1, "1µF ±20% 6.3V Ceramic Capacitor X6S 0201 (0603 Metric)", Digikey Part Number=587-6143-1-ND, MANUFACTURER="Taiyo Yuden", Mouser Part Number=963-JMK063BC6105MP-F, Operating Temperature Range="-55°C to +105°C", TempCo=22%, Temperature Characteristic=X6S, Tolerance_%=20%, ValueDisplayed=1uF
C13 C14: library part CMP-0009653-3, "CAP, CERM, 330 pF, 50 V, +/- 10%, X7R, AEC-Q200 Grade 1, 0201", Cap_Case=0201_033, MANUFACTURER=TDK, Supplier Part Number 1=445-12111-1-ND, TempCo=X7R, Tolerance_%=10%, Value1="8.05302 ohm", Value2=50V, ValueDisplayed=330pF
C16 C17: library part CMP-0860997-1, "CAP, CERM, 1000 pF, 50 V,+/- 10%, X8R, AEC-Q200 Grade 0, 0402", Cap_Case=0402, MANUFACTURER=TDK, TempCo=X8R, Tolerance_%=10%, Value2=50V, ValueDisplayed=1000pF
C18 C19: library part CMP-0079539-1, "CAP, CERM, 10 pF, 16 V,+/- 10%, C0G, 0402", Cap_Case=0402, MANUFACTURER=Kemet, Supplier Part Number 1=399-11110-1-ND, TempCo=C0G, Tolerance_%=10%, Value2=16V, ValueDisplayed=10pF
C20 C21 C22 C23: library part CMP-0006480-1, "CAP, CERM, 5 pF, 50 V, +/- 5%, C0G/NP0, 0402", Cap_Case=0402, MANUFACTURER=MuRata, Supplier Part Number 1=490-5875-1-ND, TempCo=C0G/NP0, Tolerance_%=5%, Value1=Unknown, Value2=50V, ValueDisplayed=5pF
FB1: library part CMP-0087087-1, "FERRITE BEAD 120 OHM 0402 1LN", MANUFACTURER=TDK
J1: library part CMP-0079869-1, "Header (Shrouded), 1 mm, 5x1, Tin, R/A, SMT", Color=Natural, Current_A=700mA, MANUFACTURER="JST Manufacturing", Supplier Part Number 1=455-1805-1-ND, Voltage_V=50V
R1 R3 R6 R10: library part CMP-0027004-1, "RES, 0, 5%, 0.063 W, 0402", MANUFACTURER="Yageo America", Power_W=63mW, Supplier Part Number 1=311-0.0JRCT-ND, TempCo="200 ppm/C", Tolerance_%=5%, Value2=0.063W, Value_Code=0000, ValueDisplayed=0
R2: library part CMP-0028126-1, "RES, 47.0 k, 1%, 0.05 W, AEC-Q200 Grade 0, 0201", MANUFACTURER="KOA Speer", Power_W=50mW, Supplier Part Number 1=660-RK73H1HTTC4702F, TempCo="200 ppm/C", Tolerance_%=1%, Value2=0.05W, Value_Code=47k0, ValueDisplayed=47.0k
R4: library part CMP-0065361-1, "RES, 0, 5%, .05 W, AEC-Q200 Grade 0, 0201", MANUFACTURER=Panasonic, Power_W=50mW, Supplier Part Number 1=P15979CT-ND, TempCo=ppm/C, Tolerance_%=5%, Value2=.05W, Value_Code=0000, ValueDisplayed=0
R5: library part CMP-0026815-1, "RES, 100 k, 0.1%, 0.063 W, 0402", MANUFACTURER="Susumu Co Ltd", Power_W=63mW, Supplier Part Number 1=RG10P100KBCT-ND, TempCo="25 ppm/C", Tolerance_%=0.1%, Value2=0.063W, Value_Code=100k
R7 R9 R15 R22: library part CMP-0028132-1, "RES, 100 k, 0.5%, 0.05 W, 0201", MANUFACTURER="Yageo America", Power_W=50mW, Supplier Part Number 1=RC0201DR-07100KL-ND, TempCo="200 ppm/C", Tolerance_%=0.5%, Value2=0.05W, Value_Code=100k
R8 R13 R17 R19 R20 R21 R23 R24: library part CMP-0121803-1, "10 kOhms ±0.1% 0.063W, 1/16W Chip Resistor 0402 (1005 Metric) Thin Film", Digikey Part Number=YAG4153CT-ND, MANUFACTURER=Yageo, Mouser Part Number=603-RT0402BRB0710KL, Operating Temperature Range="-55°C to +155°C", Power_W=63mW, TempCo=10ppm/°C, Tolerance_%=0.1%
R11 R18: library part CMP-0026763-1, "RES, 100, 1%, 0.063 W, AEC-Q200 Grade 0, 0402", MANUFACTURER="Stackpole Electronics Inc", Power_W=63mW, Supplier Part Number 1=RMCF0402JT100RCT-ND, TempCo="100 ppm/C", Tolerance_%=1%, Value2=0.063W, Value_Code=100R, ValueDisplayed=100
R12 R16: library part CMP-0026813-1, "RES, 5.00 k, 0.1%, 0.05 W, 0402", MANUFACTURER=Vishay-Dale, Power_W=50mW, Supplier Part Number 1=541-1901-1-ND, TempCo="25 ppm/C", Tolerance_%=0.1%, Value2=0.05W, Value_Code=5k00, ValueDisplayed=5.00k
R25: library part CMP-0028133-1, "RES, 10.0 k, 0.5%, 0.05 W, 0201", MANUFACTURER="Yageo America", Power_W=50mW, Supplier Part Number 1=RC0201DR-0710KL-ND, TempCo="200 ppm/C", Tolerance_%=0.5%, Value2=0.05W, Value_Code=10k0, ValueDisplayed=10.0k
TP1 TP2: library part CMP-0055137-1, "Test Point, Miniature, Red, TH", Color=Red, MANUFACTURER=Keystone, Supplier Part Number 1=36-5000-ND
U1: library part CMP-0086328-1, "1µA, ultra-low Iq, 200mA low-dropout (LDO) regulator in a small-size package, YKA0004AAAA (DSBGA-4)", Alternate Manufacturer="Texas Instruments", Operating Temperature Range="-40 to 125 C", Rating=Catalog
U2: library part CMP-0093963-1, "Mixed-Signal Microcontrollers with CAN-FD Interface, VQFN32", Frequency_Fixed=80MHz, MANUFACTURER="Texas Instruments", Max Supply Voltage=3.6V, Min Supply Voltage=1.62V, Operating Temperature Range="-40°C to +125°C"
U3: library part CMP-0122722-1, "650-nA quiescent current, 12-ppm/°C drift, ultra-low-power precision voltage reference 6-SOT-23 -40 to 125", Digikey Part Number=296-REF35330QDBVRCT-ND, MANUFACTURER="Texas Instruments", Max Supply Voltage=6V, Min Supply Voltage=3.55V, Mouser Part Number=595-REF35330QDBVR, Nominal Supply Current=0.65uA, Operating Temperature Range="-40°C to +125°C", Output Voltage=3.3V
U4: library part CMP-0095386-1, "Hall Effect Magnetic Sensor VSSOP8", MANUFACTURER="Texas Instruments", Max Supply Voltage=5.5V, Min Supply Voltage=2.7V, Operating Temperature Range="-40°C to +150°C"
U6: library part CMP-0077462-2, "10-MHz, Low-Noise, RRIO, CMOS Operational Amplifier for Cost-Sensitive Systems, DSG0008A (WSON-8)", Alternate Manufacturer="Texas Instruments", Alternate PartNumber=TLV9062IDSGT, Operating Temperature Range="-40 to 125 C", Rating=Catalog
U7: library part CMP-0094703-1, MANUFACTURER="Texas Instruments", Operating Temperature Range=to
U8: library part CMP-0065573-1, "Single-Bit Fixed Direction Voltage-Level Translator with Schmitt-Trigger Inputs and 3-State Outputs", Digikey Part Number=296-TXU0101DTQRCT-ND, MANUFACTURER="Texas Instruments", Mouser Part Number=595-TXU0101DTQR, Nominal Supply Current=2.5uA, Operating Temperature Range="-40°C to +125°C"
ZZ1: library part CMP-0003616-3
ZZ2: library part CMP-0077236-1
ZZ3: library part CMP-0077237-1
ZZ4: library part CMP-0077238-1

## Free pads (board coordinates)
  round 1.2 hole 0.6: 8(3.432,14.279) 8(3.432,16.152) 8(3.432,18.024) 8(3.432,19.897) 8(3.441,11.322) 8(10.784,13.541)
  rrect50% 1.55x0.6 hole 0.5: 9(23.242,16.53) 10(23.242,15.53) 11(23.242,12.531) 11(23.242,13.53) 11(23.242,14.53)
  rrect50% 1.8x1.2 smd far side: 13(27.117,17.83) 14(27.117,11.23)

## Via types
v1: diameter 0.5, hole 0.25, Top Layer to Bottom Layer, 49 vias
v2: diameter 0.5, hole 0.2, Top Layer to Bottom Layer, 11 vias

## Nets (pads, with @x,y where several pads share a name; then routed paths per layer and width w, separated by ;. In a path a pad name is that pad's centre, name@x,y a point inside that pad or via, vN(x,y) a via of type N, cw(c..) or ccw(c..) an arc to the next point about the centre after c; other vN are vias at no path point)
5V: J1.3 pad.11@23.242,14.53 R1.1 R3.1 R10.1 | length 7.2
  Top Layer w0.3: R10.1@18.384,12.573 R10.1@18.476,12.481
  Top Layer w0.508: R10.1@18.384,12.573 18.384,12.673 18.43,12.719 18.53,12.719 20.344,14.533 v1(21.995,14.533) 23.239,14.533 pad.11@23.242,14.53 23.382,14.53 pad.11@23.428,14.484
  Bottom Layer w0.508: R1.1@20.934,14.63 20.934,14.579 20.98,14.533 v1(21.995,14.533)
A: C13.2 J1.1 pad.11@23.242,12.531 R15.1 U7.8 | length 9.2
  Top Layer w0.254: U7.8@18.974,8.035 18.981,8.028 19.416,8.028 19.804,7.64 C13.2@20.395,7.64 R15.1@21.53,7.64 21.58,7.691 22.036,7.691 22.654,8.308 22.654,12.359 22.825,12.531 23.396,12.531 pad.11@23.567,12.359
B: C14.1 J1.2 pad.11@23.242,13.53 R22.2 U7.9 | length 9
  Top Layer w0.254: U7.9@18.974,8.535 18.981,8.542 19.576,8.542 19.778,8.745 C14.1@20.369,8.745 R22.2@21.504,8.745 ; R22.2@21.421,8.76 22.016,8.76 22.165,8.909 22.165,12.883 22.609,13.327 22.609,13.359 22.78,13.53 pad.11@23.242,13.53 ; pad.11@23.396,13.53 pad.11@23.567,13.359
COS: C16.1 pad.8@3.441,11.322 R11.2 U2.29 | length 5.3
  Top Layer w0.254: pad.8@3.444,11.32 4.747,11.32 R11.2@4.75,11.323 4.75,11.223 5.824,10.149 5.824,9.9 5.997,9.727 C16.1@6.097,9.727 6.19,9.82 U2.29@7.812,9.82
COS_N: R8.1 U4.3 | length 7.3
  Top Layer w0.254: v1(7.213,16.887) 9.675,14.425 U4.3@12.55,14.425
  Bottom Layer w0.254: v1(7.213,16.887) 7.213,17.754 R8.1@7.294,17.835
COS_P: R17.1 U4.1 | length 7.6
  Top Layer w0.254: v1(7.217,18.764) 10.256,15.725 U4.1@12.55,15.725
  Bottom Layer w0.254: v1(7.217,18.764) 7.217,19.689 R17.1@7.252,19.724
MCU_3V3: C3.1 C4.2 FB1.1 R2.2 U2.4 | length 3.6
  Top Layer w0.254: FB1.1@9.847,4.07 9.865,4.088 9.865,5.171 9.883,5.189 9.946,5.253 9.946,6.175 9.964,6.192 9.964,7.668 U2.4@9.962,7.67
NetC5_1: C5.1 R1.2 U1.A1 U1.B1
NetC8_2: C8.2 R3.2 U3.3 U3.4
NetC11_2: C11.2 R6.2 U4.7 | length 4.5
  Top Layer w0.254: C11.2@14.36,17.052 14.36,17.086 14.362,17.088 15.62,17.088 R6.2@15.67,17.137 15.67,15.345 15.94,15.075 U4.7@16.95,15.075
NetC12_2: C12.2 C24.2 R10.2 U7.10 U8.1 U8.5 | length 4.1
  Top Layer w0.2: R10.2@18.384,11.373 18.584,11.173 18.584,10.968 18.945,10.607 C12.2@18.945,10.265 18.945,9.055 18.965,9.035 U7.10@18.974,9.035
  Bottom Layer w0.05: U8.5@17.22,10.39 17.22,10.436 17.323,10.539 17.323,10.557 17.51,10.744 U8.1@17.595,10.744
  Bottom Layer w0.152: U8.1@17.72,10.79 U8.1@17.72,10.805
  Bottom Layer w0.2: U8.1@17.72,10.79 17.897,10.967 C24.2@18.62,10.967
